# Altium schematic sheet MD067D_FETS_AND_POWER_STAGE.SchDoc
size 431 x 279 mm; Date: Not shown in title block; ApprovedBy: Not shown in title block; CheckedBy: Not shown in title block; Author: Not shown in title block; CompanyName: Not shown in title block; Engineer: Not shown in title block; Organization: Not shown in title block; Address1: Not shown in title block; Address2: Not shown in title block; Address3: Not shown in title block; Address4: Not shown in title block; DocumentNumber: 3; Revision: Use project parameter SCH_Rev; SheetNumber: 3; SheetTotal: 5; PageSetup: Record=PageOptions¦CenterHorizontal=True¦CenterVertical=True¦PrintScale=1.00¦XCorrection=1.00¦YCorrection=1.00¦PrintKind=0¦BorderSize=5000000¦LeftOffset=0¦BottomOffset=0¦Orientation=2¦PaperLength=1000¦PaperWidth=1000¦Scale=100¦PaperSource=15¦PrintQuality=600¦MediaType=1¦DitherType=10¦PaperKind=Letter¦PrintScaleMode=1
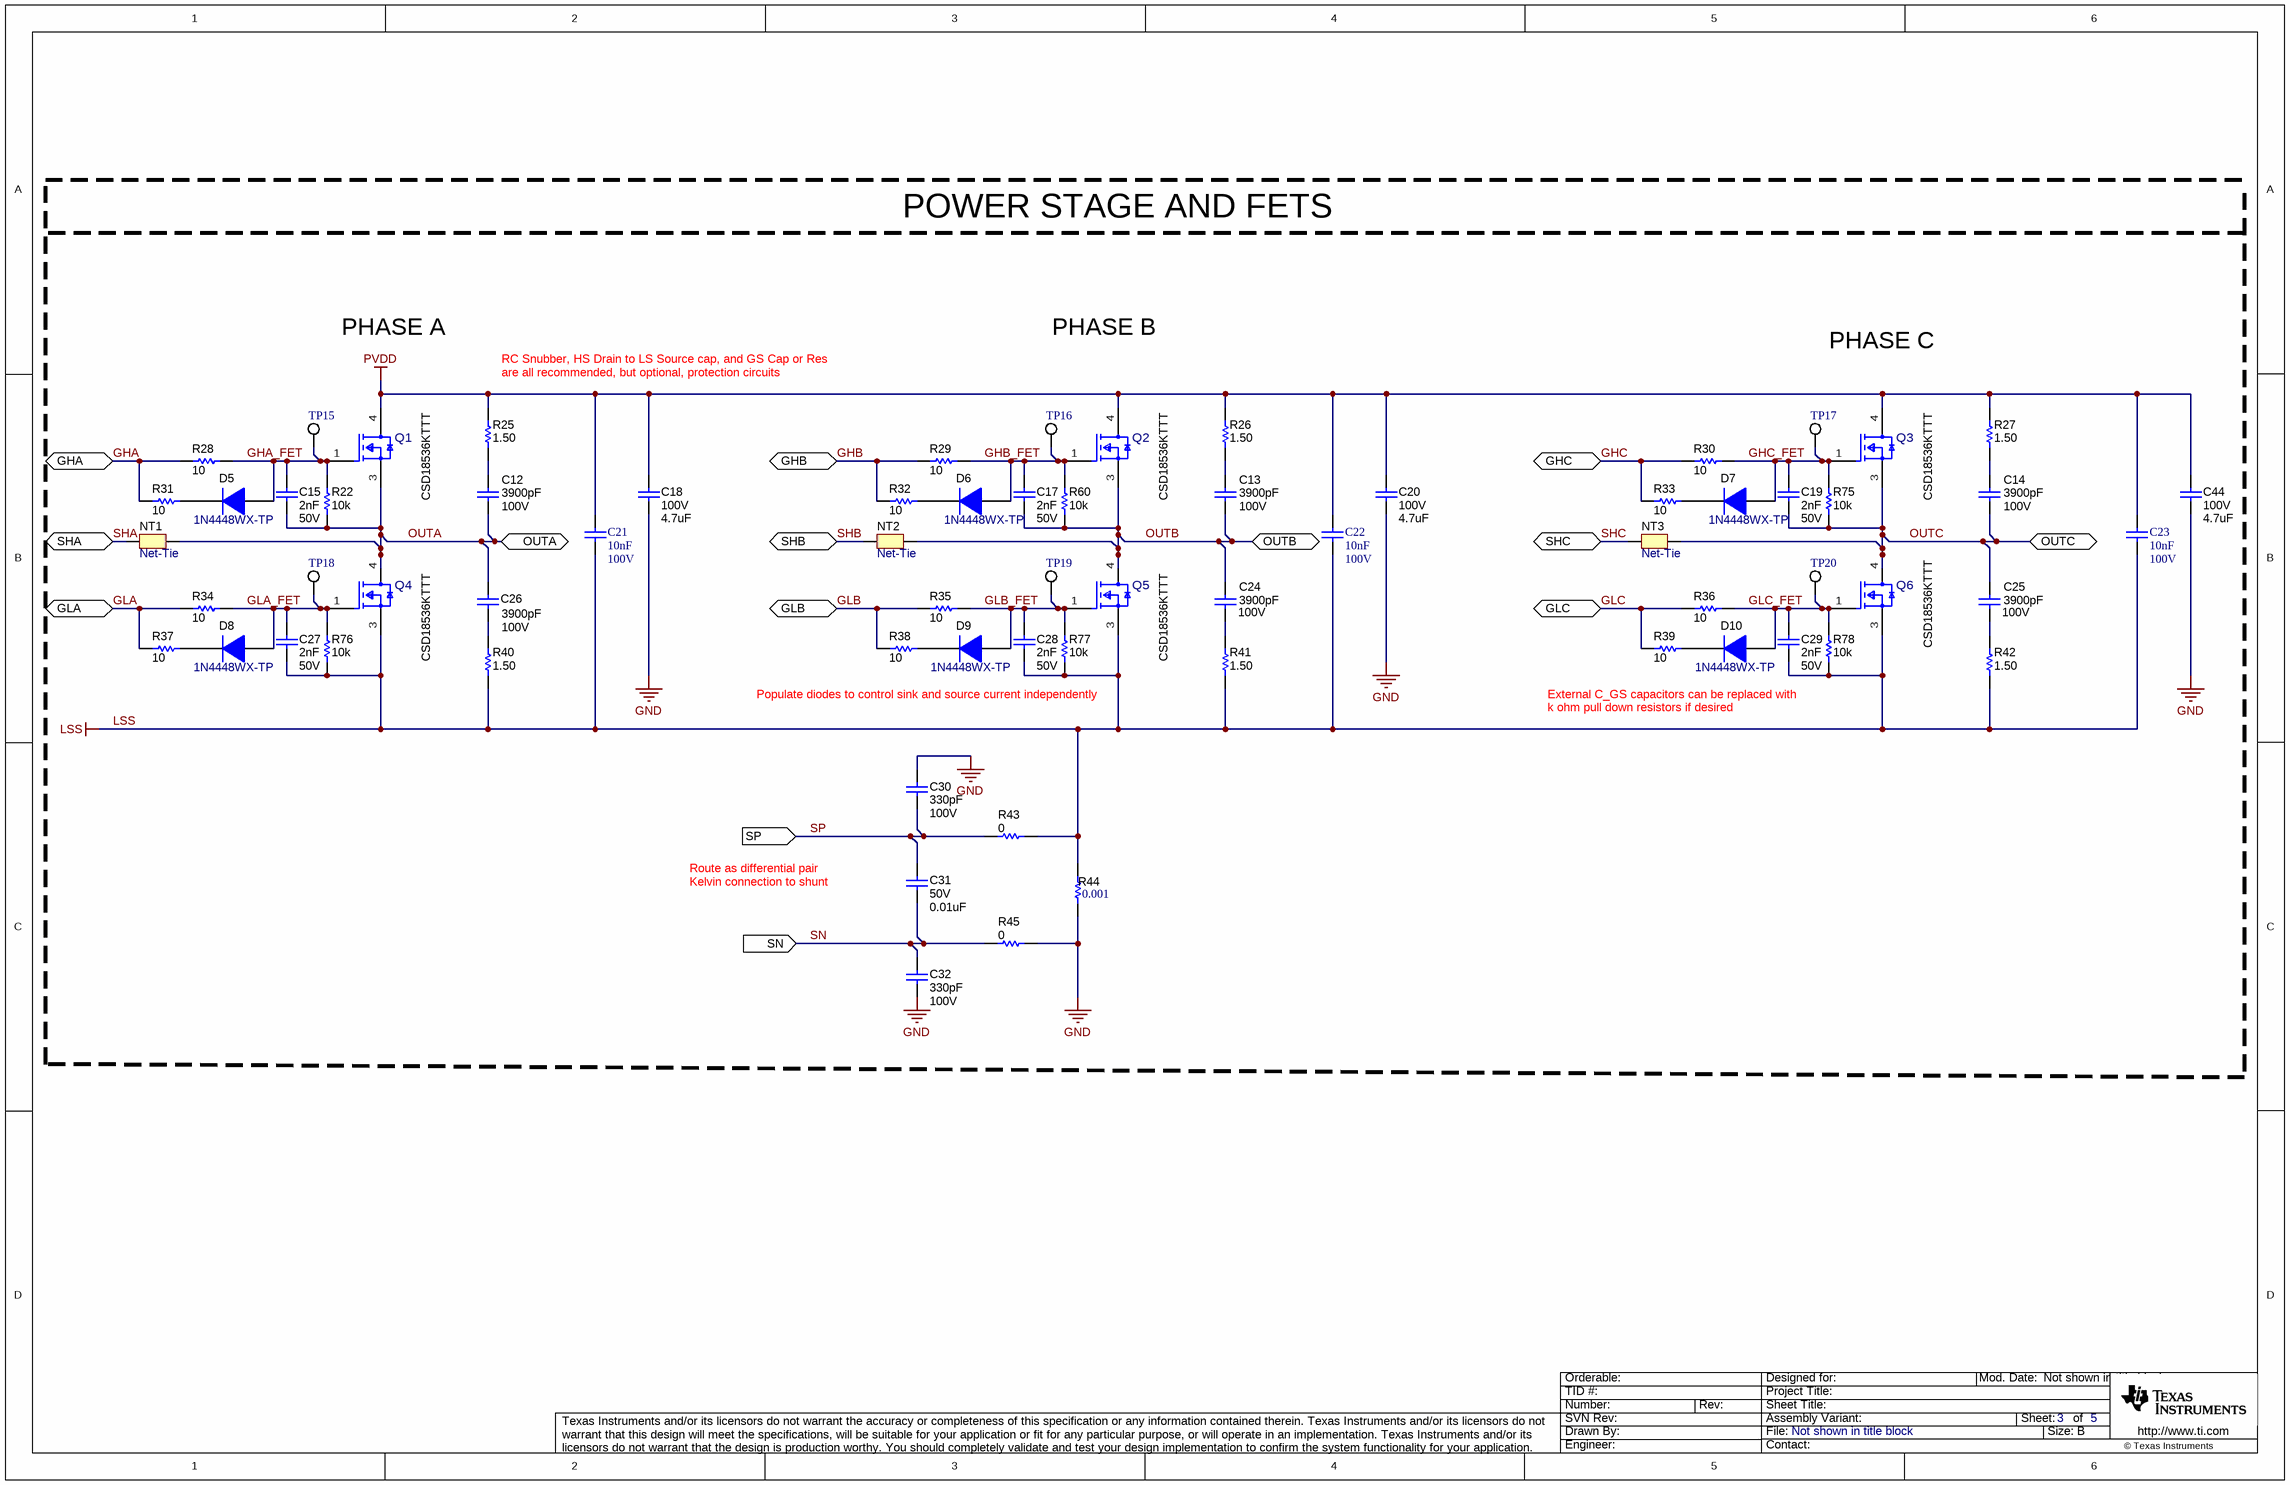
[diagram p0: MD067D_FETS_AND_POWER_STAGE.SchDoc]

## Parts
C12  VDC_V: 100V  ValueDisplayed: 3900pF  [1206L]  (hidden comment: 12061C392KAZ2A)
C13  VDC_V: 100V  ValueDisplayed: 3900pF  [1206L]  (hidden comment: 12061C392KAZ2A)
C14  VDC_V: 100V  ValueDisplayed: 3900pF  [1206L]  (hidden comment: 12061C392KAZ2A)
C15  Cap_F: 2nF  VDC_V: 50V  [0603L]  (hidden comment: GRM188R71H202KA01D)  (no BOM)
C17  Cap_F: 2nF  VDC_V: 50V  [0603L]  (hidden comment: GRM188R71H202KA01D)  (no BOM)
C18  VDC_V: 100V  ValueDisplayed: 4.7uF  [1210_220L]  (hidden comment: GRM32DC72A475KE01L)
C19  Cap_F: 2nF  VDC_V: 50V  [0603L]  (hidden comment: GRM188R71H202KA01D)  (no BOM)
C20  VDC_V: 100V  ValueDisplayed: 4.7uF  [1210_220L]  (hidden comment: GRM32DC72A475KE01L)
C21  Cap_F: 10nF  Rated Voltage (DC): 100V  [WCAP-CSGP_0805_L2W1.25H0.8_Reflow]  (hidden comment: 885012207122)
C22  Cap_F: 10nF  Rated Voltage (DC): 100V  [WCAP-CSGP_0805_L2W1.25H0.8_Reflow]  (hidden comment: 885012207122)
C23  Cap_F: 10nF  Rated Voltage (DC): 100V  [WCAP-CSGP_0805_L2W1.25H0.8_Reflow]  (hidden comment: 885012207122)
C24  VDC_V: 100V  ValueDisplayed: 3900pF  [1206L]  (hidden comment: 12061C392KAZ2A)
C25  VDC_V: 100V  ValueDisplayed: 3900pF  [1206L]  (hidden comment: 12061C392KAZ2A)
C26  VDC_V: 100V  ValueDisplayed: 3900pF  [1206L]  (hidden comment: 12061C392KAZ2A)
C27  Cap_F: 2nF  VDC_V: 50V  [0603L]  (hidden comment: GRM188R71H202KA01D)  (no BOM)
C28  Cap_F: 2nF  VDC_V: 50V  [0603L]  (hidden comment: GRM188R71H202KA01D)  (no BOM)
C29  Cap_F: 2nF  VDC_V: 50V  [0603L]  (hidden comment: GRM188R71H202KA01D)  (no BOM)
C30  Cap_F: 330pF  VDC_V: 100V  [0603L]  (hidden comment: 06031C331KAT2A)
C31  VDC_V: 50V  ValueDisplayed: 0.01uF  [0603L]  (hidden comment: C1608NP01H103J080AA)
C32  Cap_F: 330pF  VDC_V: 100V  [0603L]  (hidden comment: 06031C331KAT2A)
C44  VDC_V: 100V  ValueDisplayed: 4.7uF  [1210_220L]  (hidden comment: GRM32DC72A475KE01L)
D5  1N4448WX-TP  [SOD-323]
D6  1N4448WX-TP  [SOD-323]
D7  1N4448WX-TP  [SOD-323]
D8  1N4448WX-TP  [SOD-323]
D9  1N4448WX-TP  [SOD-323]
D10  1N4448WX-TP  [SOD-323]
NT1  Net-Tie  [Net-Tie_0805_HV_NoOverlay]  (net tie, no BOM)
NT2  Net-Tie  [Net-Tie_0805_HV_NoOverlay]  (net tie, no BOM)
NT3  Net-Tie  [Net-Tie_0805_HV_NoOverlay]  (net tie, no BOM)
Q1  CSD18536KTTT  [KTT0002A-MFG]
Q2  CSD18536KTTT  [KTT0002A-MFG]
Q3  CSD18536KTTT  [KTT0002A-MFG]
Q4  CSD18536KTTT  [KTT0002A-MFG]
Q5  CSD18536KTTT  [KTT0002A-MFG]
Q6  CSD18536KTTT  [KTT0002A-MFG]
R22  ValueDisplayed: 10k  [0603L]  (hidden comment: CRCW060310K0JNEA)
R25  ValueDisplayed: 1.50  [1206L]  (hidden comment: CRCW12061R50FKEA)
R26  ValueDisplayed: 1.50  [1206L]  (hidden comment: CRCW12061R50FKEA)
R27  ValueDisplayed: 1.50  [1206L]  (hidden comment: CRCW12061R50FKEA)
R28  ValueDisplayed: 10  [0603L]  (hidden comment: CRCW060310R0JNEA)
R29  ValueDisplayed: 10  [0603L]  (hidden comment: CRCW060310R0JNEA)
R30  ValueDisplayed: 10  [0603L]  (hidden comment: CRCW060310R0JNEA)
R31  ValueDisplayed: 10  [0603L]  (hidden comment: CRCW060310R0JNEA)
R32  ValueDisplayed: 10  [0603L]  (hidden comment: CRCW060310R0JNEA)
R33  ValueDisplayed: 10  [0603L]  (hidden comment: CRCW060310R0JNEA)
R34  ValueDisplayed: 10  [0603L]  (hidden comment: CRCW060310R0JNEA)
R35  ValueDisplayed: 10  [0603L]  (hidden comment: CRCW060310R0JNEA)
R36  ValueDisplayed: 10  [0603L]  (hidden comment: CRCW060310R0JNEA)
R37  ValueDisplayed: 10  [0603L]  (hidden comment: CRCW060310R0JNEA)
R38  ValueDisplayed: 10  [0603L]  (hidden comment: CRCW060310R0JNEA)
R39  ValueDisplayed: 10  [0603L]  (hidden comment: CRCW060310R0JNEA)
R40  ValueDisplayed: 1.50  [1206L]  (hidden comment: CRCW12061R50FKEA)
R41  ValueDisplayed: 1.50  [1206L]  (hidden comment: CRCW12061R50FKEA)
R42  ValueDisplayed: 1.50  [1206L]  (hidden comment: CRCW12061R50FKEA)
R43  ValueDisplayed: 0  [0603L]  (hidden comment: ERJ-3GEY0R00V)
R44  ValueDisplayed: 0.001  [CRE2512-R1_R4]  (hidden comment: CRE2512-FZ-R001E-3)
R45  ValueDisplayed: 0  [0603L]  (hidden comment: ERJ-3GEY0R00V)
R60  ValueDisplayed: 10k  [0603L]  (hidden comment: CRCW060310K0JNEA)
R75  ValueDisplayed: 10k  [0603L]  (hidden comment: CRCW060310K0JNEA)
R76  ValueDisplayed: 10k  [0603L]  (hidden comment: CRCW060310K0JNEA)
R77  ValueDisplayed: 10k  [0603L]  (hidden comment: CRCW060310K0JNEA)
R78  ValueDisplayed: 10k  [0603L]  (hidden comment: CRCW060310K0JNEA)
TP15  GHA_FET  [Testpoint_Keystone_Miniature]  (value not drawn)
TP16  GHB_FET  [Testpoint_Keystone_Miniature]  (value not drawn)
TP17  GHC_FET  [Testpoint_Keystone_Miniature]  (value not drawn)
TP18  GLA_FET  [Testpoint_Keystone_Miniature]  (value not drawn)
TP19  GLB_FET  [Testpoint_Keystone_Miniature]  (value not drawn)
TP20  GLC_FET  [Testpoint_Keystone_Miniature]  (value not drawn)

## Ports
GHA (bidir), GHB (bidir), GHC (bidir), GLA (bidir), GLB (bidir), GLC (bidir), OUTA (bidir), OUTB (bidir), OUTC (bidir), SHA (bidir), SHB (bidir), SHC (bidir), SN (in), SP (in)

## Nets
GND: C18.2 C20.2 C30.1 C32.2 C44.2 R44.1 R45.2
LSS: C21.1 C22.1 C23.1 C27.2 C28.2 C29.2 Q4.3(Source) Q5.3(Source) Q6.3(Source) R40.1 R41.1 R42.1 R43.2 R44.2 R76.1 R77.1 R78.1
PVDD: C18.1 C20.1 C21.2 C22.2 C23.2 C44.1 Q1.4(Drain) Q2.4(Drain) Q3.4(Drain) R25.1 R26.1 R27.1
GHA: R28.1 R31.1 ; port GHA
GHA_FET: C15.1 D5.2(A) Q1.1(Gate) R22.2 R28.2 TP15.1
GHB: R29.1 R32.1 ; port GHB
GHB_FET: C17.1 D6.2(A) Q2.1(Gate) R29.2 R60.2 TP16.1
GHC: R30.1 R33.1 ; port GHC
GHC_FET: C19.1 D7.2(A) Q3.1(Gate) R30.2 R75.2 TP17.1
GLA: R34.1 R37.1 ; port GLA
GLA_FET: C27.1 D8.2(A) Q4.1(Gate) R34.2 R76.2 TP18.1
GLB: R35.1 R38.1 ; port GLB
GLB_FET: C28.1 D9.2(A) Q5.1(Gate) R35.2 R77.2 TP19.1
GLC: R36.1 R39.1 ; port GLC
GLC_FET: C29.1 D10.2(A) Q6.1(Gate) R36.2 R78.2 TP20.1
OUTA: C12.1 C15.2 C26.1 NT1.2 Q1.3(Source) Q4.4(Drain) R22.1 ; port OUTA
OUTB: C13.1 C17.2 C24.1 NT2.2 Q2.3(Source) Q5.4(Drain) R60.1 ; port OUTB
OUTC: C14.1 C19.2 C25.1 NT3.2 Q3.3(Source) Q6.4(Drain) R75.1 ; port OUTC
SHA: NT1.1 ; port SHA
SHB: NT2.1 ; port SHB
SHC: NT3.1 ; port SHC
SN: C31.2 C32.1 R45.1 ; port SN
SP: C30.2 C31.1 R43.1 ; port SP
NetC12_2: C12.2 R25.2
NetC13_2: C13.2 R26.2
NetC14_2: C14.2 R27.2
NetC24_2: C24.2 R41.2
NetC25_2: C25.2 R42.2
NetC26_2: C26.2 R40.2
NetD5_1: D5.1(K) R31.2
NetD6_1: D6.1(K) R32.2
NetD7_1: D7.1(K) R33.2
NetD8_1: D8.1(K) R37.2
NetD9_1: D9.1(K) R38.2
NetD10_1: D10.1(K) R39.2

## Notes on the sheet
- POWER STAGE AND FETS
- PHASE A
- RC Snubber, HS Drain to LS Source cap, and GS Cap or Res
- PHASE B
- PHASE C
- (near R25) are all recommended, but optional, protection circuits
- Populate diodes to control sink and source current independently
- External C_GS capacitors can be replaced with
- k ohm pull down resistors if desired
- Route as differential pair
- Kelvin connection to shunt

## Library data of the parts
C12-C14 C24-C26 = CMP-0008756-2: CAP CER 3900PF 100V X7R 1206; Manufacturer: AVX Corporation; TaMin_C: -55°C; Polarized: N; SizeAreaWB_mm2: 10.92; Value1: Unknown; U/M: EA; TaMax_C: 125°C; Tolerance_%: 10%; SizeZ_mm: 1.35; SizeX_mm: 3.2; SizeY_mm: 1.6; Cap_Case: 1206; SizeArea_mm2: 5.12; Cap_F: 3.9nF; AEC Category: Q200
C15 C17 C19 C27-C29 = CMP-0007441-5: CAP, CERM, 2000 pF, 50 V, +/- 10%, X7R, 0603; Manufacturer: MuRata; TaMin_C: -55°C; Polarized: N; SizeAreaWB_mm2: 4.68; Value1: Unknown; U/M: EA; Value: 2000pF; TaMax_C: 125°C; SizeZ_mm: 1; SizeX_mm: 1.6; SizeY_mm: 0.8; Cap_Case: 0603; SizeArea_mm2: 1.28; AEC Category: Q200
C18 C20 C44 = CMP-0009182-2: CAP, CERM, 4.7 uF, 100 V, +/- 10%, X7S, 1210; Manufacturer: MuRata; TaMin_C: -55°C; Polarized: N; SizeAreaWB_mm2: 14.7; Value1: Unknown; U/M: EA; Value: 4.7uF; TaMax_C: 125°C; SizeZ_mm: 2.2; SizeX_mm: 3.2; SizeY_mm: 2.5; Cap_Case: 1210; SizeArea_mm2: 8; Cap_F: 4.7µF; AEC Category: Q200
C21-C23 = CMP-0108439-1: WCAP-CSGP Multilayer Ceramic Chip Capacitor, General Purpose, size 0805, X7R, 10nF, 100VDC; Manufacturer: Wurth Elektronik; Capacitance Tolerance: +/-10%; Case/Size Code: 0805; Dissipation Factor: 2.5%; Insulation Resistance: 10GOhm; Technical Reference: X7R0805103K100DFCT10000; Value: 0.01uF
C30 C32 = CMP-0006740-4: CAP, CERM, 330 pF, 100 V, +/- 10%, X7R, 0603; Manufacturer: AVX; TaMin_C: -55°C; ESR_ohm: 0.472; Polarized: N; SizeAreaWB_mm2: 4.68; Value1: 0.472 ohm; U/M: EA; Value: 330pF; TaMax_C: 125°C; SizeZ_mm: 1; SizeX_mm: 1.6; SizeY_mm: 0.8; Cap_Case: 0603; SizeArea_mm2: 1.28; AEC Category: Q200
C31 = CMP-0006998-4: CAP, CERM, 0.01 uF, 50 V, +/- 5%, C0G/NP0, 0603; Manufacturer: TDK; TaMin_C: -55°C; Polarized: N; SizeAreaWB_mm2: 4.68; Value1: Unknown; U/M: EA; Value: 0.01uF; TaMax_C: 150°C; SizeZ_mm: 1; SizeX_mm: 1.6; SizeY_mm: 0.8; Cap_Case: 0603; SizeArea_mm2: 1.28; Cap_F: 10nF; AEC Category: Q200
D5-D10 = CMP-0076911-2: Diode, Switching, 75 V, 0.25 A, SOD-323; Manufacturer: Micro Commercial Components; SizeArea_mm2: 3.645; TJmax_C: 150°C; Vr_V: 75V; SizeY_mm: 1.35; Value: 75V; SizeAreaWB_mm2: 8.695; Green_Lifecycle: Not Set; SizeX_mm: 2.7; AEC Category: Q101; Io_A: 250mA; Green_REACh: Incomplete; Value1: 0.25A; SizeZ_mm: 1.0
NT1-NT3 = CMP-0078142-2: Single point connection between nets.
Q1-Q6 = CMP-0092295-1: MOSFET 60-V, N channel NexFET power MOSFET, single D2PAK, 1.6 mOhm 3-DDPAK/TO-263 -55 to 175; Manufacturer: Texas Instruments; QgTyp_nC: 108nC @ 10V; Threshold Vgs Min: 1.4V; VdsMax_V: 1V; Standoff Height: 0mm; Rdson45_ohm: 1.3m; Reverse Recovery Time: 86ns; ChMode: False; Turn On Delay Time: 11ns; Typ Forward Diode Voltage: 0.9V; Transconductance: 312S; Threshold Vgs Max: 2.2V; Rthja Max: 62°C/W; Drain To Source Breakdown Voltage: 60V; Reverse Recovery Charge: 323nC; TJmax_C: +175°C; AEC Qualified: No; Power_W: 375W; Turn Off Delay Time: 24ns; Number Of Channels: 1; Vgs_V: 20V; SizeZ_mm: 4.95mm; Pulse Drain Current: 400A; IdsMax_A: 200A; Input Capacitace At Vds: 8790pF @ 30V
R22 R60 R75-R78 = CMP-0025701-2: RES, 10 k, 5%, 0.1 W, 0603; Manufacturer: Vishay-Dale; Power_W: 100mW; TempCo: 200 ppm/C; Value_Code: 10k0; U/M: EA; Value: 10k; EIA_Code: E24; SizeX_mm: 1.6; SizeY_mm: 0.8; SizeZ_mm: 1; Value2: 0.1W; SizeArea_mm2: 1.28; VDC_V: 75V; AEC Category: Q200
R25-R27 R40-R42 = CMP-0016763-3: RES, 1.50, 1%, 0.25 W, AEC-Q200 Grade 0, 1206; Manufacturer: Vishay-Dale; Power_W: 250mW; TempCo: 100 ppm/C; Value_Code: 1R50; Value: 1.50; EIA_Code: E96; Res_ohm: 1.5; SizeX_mm: 3.2; SizeY_mm: 1.6; SizeZ_mm: 1.35; Value2: 0.25W; SizeArea_mm2: 5.12; AEC Qualified: Y; VDC_V: 200V; AEC Category: Q200; AEC Grade: 0
R28-R39 = CMP-0025703-4: RES, 10, 5%, 0.1 W, AEC-Q200 Grade 0, 0603; Manufacturer: Vishay-Dale; Power_W: 100mW; TempCo: 200 ppm/C; Value_Code: 10R0; Value: 10; EIA_Code: E24; SizeX_mm: 1.6; SizeY_mm: 0.8; SizeZ_mm: 1; Value2: 0.1W; SizeArea_mm2: 1.28; AEC Qualified: Y; VDC_V: 75V; AEC Category: Q200; AEC Grade: 0
R43 R45 = CMP-0025874-4: RES, 0, 5%, 0.1 W, AEC-Q200 Grade 0, 0603; Manufacturer: Panasonic; Power_W: 100mW; TempCo: 600 ppm/C; Value_Code: 0000; Value: 0; EIA_Code: E24; SizeX_mm: 1.6; SizeY_mm: 0.8; SizeZ_mm: 1; Value2: 0.1W; SizeArea_mm2: 1.28; AEC Qualified: Y; VDC_V: 50V; AEC Category: Q200; SizeAreaWB_mm2: 4.68
R44 = CMP-0015748-2: RES, 0.001, 1%, 3 W, AEC-Q200 Grade 0, 2512; Manufacturer: Bourns; Power_W: 3W; TempCo: 50 ppm/C; Value_Code: 1L000; U/M: EA; Value: 0.001; EIA_Code: E96; Res_ohm: 1m; SizeX_mm: 6.45; SizeY_mm: 3.35; SizeZ_mm: 0.9; SizeArea_mm2: 21.6075; AEC Qualified: Y; AEC Grade: 0; AEC Category: Q200
TP15-TP20 = CMP-0055152-1: Test Point, Miniature, SMT; Manufacturer: Keystone; CNHeader: FALSE; Green_Lifecycle: Active; Green_REACh: Passed; CT: TRUE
